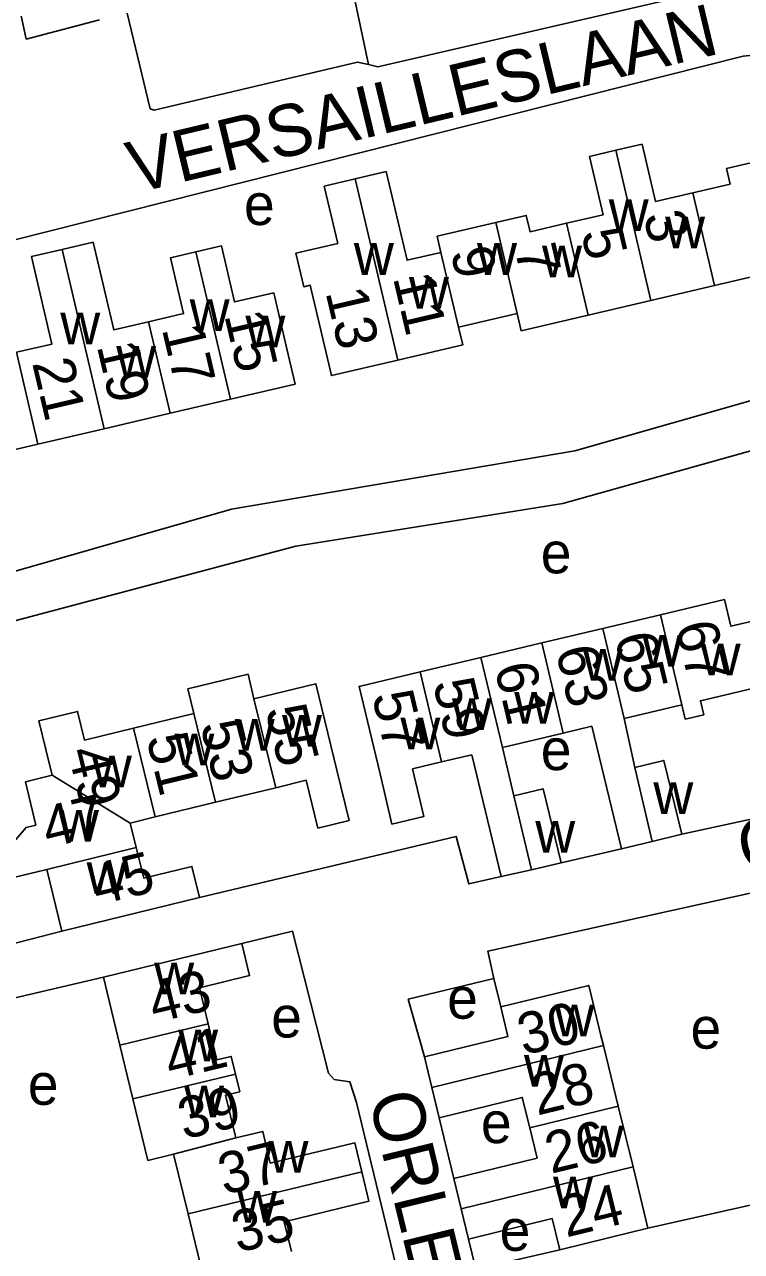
# Model space of a CAD drawing. Extents: x 157768 to 159790, y 387230 to 389604.
# Drawn here: x 159107.4 to 159176.8, y 388362 to 388480.9 of the extents above; entities that cross this region are included whole.
import ezdxf

# ---------------------------------------------------------------- set-up
doc = ezdxf.new("R2010")
doc.units = 0
for name, color, linetype in [('BLT_Basislijn', 7, 'Continuous'), ('BLT_Bebouwing', 7, 'Continuous'), ('BLT_Centroide', 7, 'Continuous'), ('BLT_Huisnummer', 7, 'Continuous'), ('BLT_Huisnummer_ tussenligend', 7, 'Continuous'), ('BLT_Onderverdeling_panden', 7, 'Continuous'), ('BLT_Straatnaam', 7, 'Continuous')]:
    doc.layers.add(name, color=color, linetype=linetype)

msp = doc.modelspace()

# ---------------------------------------------------------------- linework, layer by layer
at = {"layer": 'BLT_Basislijn'}
for p, q in [((159138.77, 388486.21), (159140.71, 388477.01)), ((159159.36, 388399.68), (159165.22, 388401.05)), ((159153.52, 388385.74), (159152.87, 388388.5)), ((159147.58, 388375), (159148.97, 388369.12)), ((159167.78, 388364.29), (159185.74, 388368.37)), ((159151.11, 388360.32), (159150.4, 388363.25)), ((159159.25, 388362.21), (159151.11, 388360.32))]:
    msp.add_line(p, q, dxfattribs=at)
for points in [[(159106.86, 388505.71), (159102.12, 388504.46), (159103.16, 388500), (159107.59, 388479.48), (159114.69, 388481.34)], [(159140.71, 388477.01), (159141.64, 388476.78), (159181.77, 388486.09), (159182.83, 388486.01), (159183.84, 388482.19), (159184.32, 388481.76), (159218.82, 388489.66)], [(159117.36, 388481.98), (159119.6, 388472.73), (159119.99, 388472.6), (159139.65, 388477.25), (159140.71, 388477.01)], [(159183.75, 388474.26), (159179.89, 388473.78), (159178.57, 388477.97), (159176.99, 388477.81), (159106.11, 388459.93)], [(159183.75, 388474.26), (159189.25, 388449.23), (159188.87, 388447.64), (159160.69, 388439.6), (159127.47, 388433.94), (159100.65, 388426.26)], [(159189.35, 388442.87), (159159.54, 388434.5), (159133.68, 388430.36), (159100.76, 388421.61)], [(159171.05, 388402.47), (159191.76, 388406.94), (159191.46, 388408.16), (159197.34, 388409.62)], [(159124.37, 388396.32), (159149.2, 388402.25), (159150.44, 388397.65), (159153.57, 388398.35)], [(159152.87, 388388.5), (159152.26, 388391.13), (159178.99, 388397.04)], [(159097.88, 388389.74), (159100, 388390.23), (159111.04, 388393.07)], [(159148.42, 388319.19), (159153.14, 388320.25), (159139.56, 388376.46), (159138.93, 388378.48), (159137.41, 388378.7), (159136.86, 388379.32), (159133.36, 388393.08), (159128.47, 388391.87)], [(159115.06, 388388.62), (159100, 388385.11), (159099.78, 388385.06)], [(159152.87, 388388.5), (159144.57, 388386.49), (159146.14, 388380.89)]]:
    msp.add_lwpolyline(points, dxfattribs=at)
at = {"layer": 'BLT_Bebouwing'}
for p, q in [((159174.21, 388455.6), (159168.06, 388454.16)), ((159168.06, 388454.16), (159161.98, 388452.74)), ((159155.1, 388452.89), (159149.44, 388451.56)), ((159127.36, 388444.59), (159121.52, 388443.23)), ((159121.52, 388443.23), (159115.14, 388441.74)), ((159115.14, 388441.74), (159108.72, 388440.24)), ((159108.72, 388440.24), (159102.76, 388438.84)), ((159168.99, 388423.72), (159163.4, 388422.39)), ((159163.4, 388422.39), (159157.51, 388420.99)), ((159157.51, 388420.99), (159151.61, 388419.59)), ((159151.61, 388419.59), (159145.72, 388418.18)), ((159171.06, 388414.99), (159165.48, 388413.66)), ((159117.98, 388412.73), (159123.81, 388414.15)), ((159165.48, 388413.66), (159166.51, 388408.93)), ((159154.8, 388406.19), (159153.69, 388410.86)), ((159125.91, 388405.55), (159131.74, 388406.97)), ((159120.08, 388404.13), (159125.91, 388405.55)), ((159117.66, 388403.54), (159120.08, 388404.13)), ((159118.24, 388401.16), (159117.66, 388403.54)), ((159168.2, 388401.77), (159165.22, 388401.05)), ((159171.05, 388402.47), (159168.2, 388401.77)), ((159159.36, 388399.68), (159156.5, 388399.02)), ((159111.04, 388393.07), (159109.58, 388399.05)), ((159156.5, 388399.02), (159153.57, 388398.35)), ((159111.04, 388393.07), (159124.37, 388396.32)), ((159115.06, 388388.62), (159128.47, 388391.87)), ((159116.66, 388382.03), (159117.92, 388376.82)), ((159163.46, 388382), (159164.9, 388376.11)), ((159146.14, 388380.89), (159146.86, 388377.94)), ((159146.86, 388377.94), (159147.58, 388375)), ((159164.9, 388376.11), (159166.33, 388370.25)), ((159121.86, 388371.47), (159123.27, 388365.68)), ((159166.33, 388370.25), (159167.78, 388364.29)), ((159148.97, 388369.12), (159149.69, 388366.19)), ((159149.69, 388366.19), (159150.4, 388363.25)), ((159123.27, 388365.68), (159124.65, 388359.96))]:
    msp.add_line(p, q, dxfattribs=at)
for points in [[(159159.9, 388461.64), (159163.44, 388462.47), (159162.12, 388468.11), (159164.66, 388468.71)], [(159164.66, 388468.71), (159167.21, 388469.3), (159168.51, 388463.74), (159172.12, 388464.58)], [(159172.12, 388464.58), (159175.73, 388465.43), (159175.37, 388466.93), (159181.19, 388468.29), (159183.41, 388458.79), (159180.23, 388458.05), (159180.46, 388457.06), (159174.21, 388455.6)], [(159143.55, 388448.38), (159137.13, 388446.88), (159136.2, 388450.85), (159135.08, 388455.63), (159134.45, 388455.49), (159133.69, 388458.74), (159137.74, 388459.68), (159136.44, 388465.23), (159139.44, 388465.93)], [(159139.44, 388465.93), (159142.45, 388466.64), (159144.46, 388458.05), (159147.74, 388458.82)], [(159153.04, 388461.71), (159156, 388462.4), (159156.37, 388460.81), (159159.9, 388461.64)], [(159147.74, 388458.82), (159147.38, 388460.38), (159153.04, 388461.71)], [(159106.64, 388449.14), (159110.07, 388449.94), (159108.09, 388458.41), (159111.08, 388459.1)], [(159111.08, 388459.1), (159114.07, 388459.8), (159116.06, 388451.31), (159119.44, 388452.1)], [(159119.44, 388452.1), (159122.83, 388452.89), (159121.56, 388458.3), (159124.02, 388458.87)], [(159124.02, 388458.87), (159126.48, 388459.45), (159127.75, 388454.02), (159131.55, 388454.9), (159132.69, 388450.04), (159133.62, 388446.06), (159127.36, 388444.59)], [(159161.98, 388452.74), (159155.49, 388451.22), (159155.1, 388452.89)], [(159149.44, 388451.56), (159149.84, 388449.85), (159143.55, 388448.38)], [(159178.33, 388423.2), (159175.81, 388422.6), (159175.19, 388425.19), (159168.99, 388423.72)], [(159123.81, 388414.15), (159123.23, 388416.53), (159129.06, 388417.95), (159129.64, 388415.57)], [(159145.72, 388418.18), (159139.82, 388416.78), (159141.84, 388408.31), (159142.99, 388403.45), (159146.09, 388404.18), (159144.99, 388408.79), (159147.79, 388409.46)], [(159129.64, 388415.57), (159135.61, 388417.03), (159137.65, 388408.65), (159138.84, 388403.79), (159135.83, 388403.06), (159134.7, 388407.69), (159131.74, 388406.97)], [(159179.79, 388417.04), (159172.86, 388415.39), (159173.18, 388414.04), (159171.39, 388413.62), (159171.06, 388414.99)], [(159110.1, 388408.17), (159109.49, 388410.66), (159108.81, 388413.44), (159112.57, 388414.36), (159113.24, 388411.58), (159117.98, 388412.73)], [(159165.22, 388401.05), (159162.33, 388412.92), (159159.58, 388412.26)], [(159159.58, 388412.26), (159153.69, 388410.86)], [(159153.57, 388398.35), (159150.72, 388410.15), (159147.79, 388409.46)], [(159166.51, 388408.93), (159169.31, 388409.61), (159171.05, 388402.47)], [(159108.53, 388403.35), (159107.51, 388407.53), (159110.1, 388408.17)], [(159154.8, 388406.19), (159157.62, 388406.87), (159159.36, 388399.68)], [(159109.58, 388399.05), (159106.22, 388398.23), (159105.73, 388400.25), (159106.41, 388401.74), (159107.58, 388403.12), (159108.53, 388403.35)], [(159124.37, 388396.32), (159123.63, 388399.34), (159118.96, 388398.21), (159118.24, 388401.16)], [(159128.47, 388391.87), (159129.22, 388388.77), (159124.35, 388387.59), (159125.2, 388384.1)], [(159116.66, 388382.03), (159116.24, 388383.77), (159115.06, 388388.62)], [(159163.46, 388382), (159163.23, 388382.96), (159162.04, 388387.82), (159153.52, 388385.74)], [(159153.52, 388385.74), (159154.22, 388382.86), (159146.14, 388380.89)], [(159125.2, 388384.1), (159126.04, 388380.6), (159127.43, 388380.94), (159127.84, 388379.23)], [(159127.84, 388379.23), (159128.26, 388377.52), (159126.89, 388377.18), (159127.89, 388373.05)], [(159117.92, 388376.82), (159119.37, 388370.86), (159121.86, 388371.47)], [(159147.58, 388375), (159155.61, 388376.96), (159156.33, 388374.02)], [(159127.89, 388373.05), (159130.48, 388373.68), (159131.22, 388370.6), (159139.4, 388372.58), (159140.08, 388369.75)], [(159156.33, 388374.02), (159157.04, 388371.09), (159148.97, 388369.12)], [(159140.08, 388369.75), (159140.77, 388366.92), (159132.56, 388364.93), (159133.26, 388362.04)], [(159150.4, 388363.25), (159158.51, 388365.23), (159159.25, 388362.21)], [(159159.25, 388362.21), (159164.1, 388363.39), (159167.78, 388364.29)]]:
    msp.add_lwpolyline(points, dxfattribs=at)
at = {"layer": 'BLT_Onderverdeling_panden'}
for p, q in [((159164.66, 388468.71), (159168.06, 388454.16)), ((159139.44, 388465.93), (159143.55, 388448.38)), ((159172.12, 388464.58), (159174.21, 388455.6)), ((159153.04, 388461.71), (159155.1, 388452.89)), ((159159.9, 388461.64), (159161.98, 388452.74)), ((159111.08, 388459.1), (159115.14, 388441.74)), ((159124.02, 388458.87), (159127.36, 388444.59)), ((159147.74, 388458.82), (159149.44, 388451.56)), ((159119.44, 388452.1), (159121.52, 388443.23)), ((159106.64, 388449.14), (159108.72, 388440.24)), ((159171.06, 388414.99), (159168.99, 388423.72)), ((159165.48, 388413.66), (159163.4, 388422.39)), ((159159.58, 388412.26), (159157.51, 388420.99)), ((159153.69, 388410.86), (159151.61, 388419.59)), ((159147.79, 388409.46), (159145.72, 388418.18)), ((159131.74, 388406.97), (159129.64, 388415.57)), ((159125.91, 388405.55), (159123.81, 388414.15)), ((159120.08, 388404.13), (159117.98, 388412.73)), ((159168.2, 388401.77), (159166.51, 388408.93)), ((159110.1, 388408.17), (159117.66, 388403.54)), ((159156.5, 388399.02), (159154.8, 388406.19)), ((159109.58, 388399.05), (159118.24, 388401.16)), ((159125.2, 388384.1), (159116.66, 388382.03)), ((159146.86, 388377.94), (159163.46, 388382)), ((159127.84, 388379.23), (159117.92, 388376.82)), ((159156.33, 388374.02), (159164.9, 388376.11)), ((159127.89, 388373.05), (159121.86, 388371.47)), ((159140.08, 388369.75), (159123.27, 388365.68)), ((159149.69, 388366.19), (159166.33, 388370.25))]:
    msp.add_line(p, q, dxfattribs=at)

# ---------------------------------------------------------------- texts
at = {"layer": 'BLT_Centroide'}
for s, p in [('e', (159128.67, 388461.47)), ('w', (159163.98, 388460.89)), ('w', (159169.44, 388459.22)), ('w', (159139.31, 388456.64)), ('w', (159151.23, 388456.64)), ('w', (159157.52, 388456.39)), ('w', (159144.64, 388453.36)), ('w', (159123.41, 388451.19)), ('w', (159110.89, 388449.91)), ('w', (159128.81, 388449.61)), ('w', (159116.3, 388446.69)), ('e', (159157.4, 388427.73)), ('w', (159167.23, 388418.7)), ('w', (159172.88, 388417.84)), ('w', (159161.48, 388417.33)), ('w', (159154.83, 388413.16)), ('w', (159148.8, 388412.56)), ('w', (159127.78, 388410.56)), ('w', (159132.35, 388410.95)), ('w', (159143.81, 388410.69)), ('w', (159121.94, 388409.14)), ('e', (159157.4, 388408.67)), ('w', (159113.95, 388407)), ('w', (159168.3, 388404.41)), ('w', (159110.76, 388401.73)), ('w', (159156.87, 388400.68)), ('w', (159113.44, 388396.66)), ('w', (159119.98, 388386.94)), ('e', (159148.34, 388384.59)), ('e', (159131.31, 388382.77)), ('w', (159158.73, 388382.88)), ('e', (159171.9, 388381.69)), ('w', (159122.3, 388380.47)), ('w', (159155.78, 388378)), ('e', (159107.75, 388376.25)), ('w', (159122.88, 388375.03)), ('e', (159151.61, 388372.54)), ('w', (159161.57, 388371.16)), ('w', (159131.05, 388369.69)), ('w', (159158.59, 388366.22)), ('w', (159128.02, 388364.84)), ('e', (159153.42, 388362.11))]:
    msp.add_text(s, height=4, dxfattribs=at).set_placement(p)
at = {"layer": 'BLT_Huisnummer'}
for s, rotation, p in [('5', 283.1491, (159161.29, 388460.74)), ('9', 283.1491, (159148.65, 388458.9)), ('13', 283.1491, (159136.55, 388454.96)), ('15', 283.1491, (159126.75, 388452.74)), ('19', 283.1491, (159114.41, 388449.76)), ('65', 283.3733, (159164.52, 388421.57)), ('61', 283.3747, (159152.89, 388418.65)), ('57', 283.3739, (159141.04, 388415.91)), ('55', 283.688, (159130.71, 388414.53)), ('49', 283.7012, (159111.59, 388410.5)), ('47', 13.6949, (159109.69, 388401.1)), ('45', 13.6919, (159114.48, 388395.56)), ('43', 13.6138, (159120, 388384.15)), ('30', 13.7143, (159155.72, 388381.03)), ('37', 13.6138, (159126.74, 388367.51)), ('24', 13.7134, (159159.86, 388363.39))]:
    msp.add_text(s, height=4, rotation=rotation, dxfattribs=at).set_placement(p)
at = {"layer": 'BLT_Huisnummer_ tussenligend'}
for s, rotation, p in [('3', 283.1491, (159167.32, 388462.39)), ('7', 283.1491, (159154.85, 388459.15)), ('11', 283.1491, (159143.08, 388456.38)), ('17', 283.1491, (159120.71, 388451.41)), ('21', 283.1491, (159108.15, 388448.12)), ('67', 283.3733, (159170.42, 388422.66)), ('63', 283.3747, (159158.82, 388420.29)), ('59', 283.3739, (159146.94, 388417.11)), ('53', 283.6958, (159124.42, 388413.07)), ('51', 283.6958, (159119.2, 388411.78)), ('41', 13.6138, (159121.55, 388378.63)), ('28', 13.7134, (159157.05, 388375.2)), ('39', 13.6138, (159122.85, 388372.88)), ('26', 13.7134, (159158.39, 388369.56)), ('35', 13.6138, (159128.05, 388361.91))]:
    msp.add_text(s, height=4, rotation=rotation, dxfattribs=at).set_placement(p)
at = {"layer": 'BLT_Straatnaam'}
for s, rotation, p in [('VERSAILLESLAAN', 13.4533, (159118.1, 388464.52)), ('ORLEANSHOF', 13.7061, (159177.17, 388398.61)), ('ORLEANSHOF', 283.71, (159140.71, 388376.98))]:
    msp.add_text(s, height=5, rotation=rotation, dxfattribs=at).set_placement(p)

doc.saveas('drawing.dxf')
